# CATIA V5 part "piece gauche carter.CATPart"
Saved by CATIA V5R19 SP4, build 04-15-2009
Part number: piece gauche carter
Bounding box of the stored display mesh (mm): x 0 to 17.7, y -143.505 to 592.858, z -82.118 to 132.474
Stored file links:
  G:\EU_thinkMotion\CFAO_2010\MMS_groupe1\MMS_groupe1\A reprendre\OK\rdeneffle\piece gauche carter.CATPart
  G:\EU_thinkMotion\CFAO_2010\MMS_groupe1\MMS_groupe1\A reprendre\OK\rdeneffle\piece haute carter.CATPart
  G:\EU_thinkMotion\CFAO_2010\MMS_groupe1\MMS_groupe1\A reprendre\OK\rdeneffle\systeme d'ouverture de porte de voiture.CATProduct
  G:\EU_thinkMotion\CFAO_2010\MMS_groupe1\MMS_groupe1\A reprendre\OK\rdeneffle\squelette.CATPart
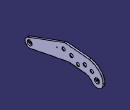
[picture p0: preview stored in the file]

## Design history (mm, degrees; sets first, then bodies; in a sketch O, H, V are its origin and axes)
Set1
  Line1 to Line6: linked copy from another document
Body1 (main body)
Body2
  Sketch1 on yz-plane, origin (0, 0, 0), H (0, 1, 0), V (0, 0, 1)
    line L1 (-115.8569, 5.5867) -> (231.1101, 133.3715)
    line L2 (-92.9007, -75.9825) -> (265.6157, -4.8754)
    arc A1 centre (-101.169, -34.2945) radius 42.5 from (-115.8569, 5.5867) to (-92.9007, -75.9825) ccw
    point P5 (-101.169, -34.2945)
    line L3 (231.1101, 133.3715) -> (463.899, 112.1961)
    point P6 (463.899, 112.1961)
    line L4 (265.6157, -4.8754) -> (417.9866, -18.7357)
    point P7 (417.9866, -18.7357)
    point P8 (535.8579, -25.2291)
    point P9 (498.4495, -68.2362)
    point P10 (573.2442, 17.7972)
    spline S1 through (463.899, 112.1961) (517.8359, 90.8537) (573.2442, 39.8908) (592.8579, -25.2291)
    spline S2 through (417.9866, -18.7357) (442.583, -22.9106) (473.0665, -41.2867) (498.4495, -68.2362) (498.4495, -68.2362)
    arc A2 centre (535.8579, -25.2291) radius 57 from (498.4495, -68.2362) to (592.8579, -25.2291) ccw
    point P12 (592.8579, -25.2291)
    point P13 (463.899, 112.1961)
    point P14 (592.8579, -25.2291)
    point P15 (417.9866, -18.7357)
    point P19 (498.4495, -68.2362)
    radius A1 = 42.5
    length L2 = 365.5
    angle L1 L2 = 9
    length L1 = 369.75
    length L3 = 233.75
    length L4 = 153
    distance P8 P6 = 155.125
    distance P7 P8 = 118.05
    radius A2 = 57
    distance P8 P5 = 637.0914
    tangency: A1 L1, L2 A1
    parallelism: L4 L3
    coincidence: P13 P6, P15 P7, P19 P9, A2 P10, P14 P12
  Pad1: profile Sketch1, direction (1, 0, 0), length 17.7
  Fillet1: radius 50, on edge [face of Pad1 from Sketch1.L1 | face of Pad1 from Sketch1.L3]
  Fillet2: radius 50, on edge [face of Pad1 from Sketch1.L4 | face of Pad1 from Sketch1.L2]
  Sketch2 on end face of Pad1, origin (17.7, 0, 0), H (0, 1, 0), V (0, 0, 1)
    circle A1 centre (535.8579, -25.2291) radius 13
    circle A2 centre (-101.169, -34.2945) radius 13
    reference projected arc E1 centre (-101.169, -34.2945) radius 42.5 from (-115.8569, 5.5867) to (-92.9007, -75.9825) ccw from edge [face of Pad1 from Sketch1.A1 | end face of Pad1]
    reference projected arc E2 centre (535.8579, -25.2291) radius 57 from (498.4495, -68.2362) to (592.8579, -25.2291) ccw from edge [face of Pad1 from Sketch1.A2 | end face of Pad1]
    radius A2 = 13
    radius A1 = 13
    concentricity: A2 E1, A1 E2
  Pocket1: profile Sketch2, direction (-1, 0, 0), length 17.7
  DatumCurve1
  Sketch3 on end face of Pad1, origin (17.7, 0, 0), H (0, 1, 0), V (0, 0, 1)
    circle A1 centre (-101.1686, -34.2944) radius 23.5
    reference projected circle E1 centre (-101.1686, -34.2944) radius 43 from edge of DatumCurve1
    radius A1 = 23.5
    concentricity: A1 E1
  Pocket2: profile Sketch3, direction (-1, 0, 0), length 13
  DatumCurve2
  Sketch4 on end face of Pad1, origin (17.7, 0, 0), H (0, 1, 0), V (0, 0, 1)
    circle A1 centre (535.8579, -25.2291) radius 23.5
    reference projected circle E1 centre (535.8579, -25.2291) radius 57 from edge of DatumCurve2
    radius A1 = 23.5
    concentricity: A1 E1
  Pocket3: profile Sketch4, direction (-1, 0, 0), length 13
  Sketch5 on end face of Pad1, origin (17.7, 0, 0), H (0, 1, 0), V (0, 0, 1)
    circle A1 centre (157.8475, 60.0892) radius 3.85
    point P1 (157.8475, 60.0892)
    circle A2 centre (219.6815, 76.7132) radius 15.505
    point P2 (219.6815, 76.7132)
    circle A3 centre (294.2515, 59.9231) radius 15.505
    point P3 (294.2515, 59.9231)
    circle A4 centre (356.8944, 18.1521) radius 15.505
    point P4 (356.8944, 18.1521)
    circle A5 centre (421.9525, 48.624) radius 15.505
    point P5 (421.9525, 48.624)
    circle A6 centre (488.2504, 26.056) radius 15.505
    point P6 (488.2504, 26.056)
    reference projected point E1 (157.8475, 60.0892) from Line1
    reference projected point E2 (219.6815, 76.7132) from Line2
    reference projected point E3 (294.2515, 59.9231) from Line3
    reference projected point E4 (356.8944, 18.1521) from Line4
    reference projected point E5 (421.9525, 48.624) from Line5
    reference projected point E6 (488.2504, 26.056) from Line6
    radius A1 = 3.85
    radius A2 = 15.505
    radius A3 = 15.505
    radius A4 = 15.505
    radius A5 = 15.505
    radius A6 = 15.505
    coincidence: P1 E1, P2 E2, P3 E3, P4 E4, P5 E5, E6 P6
  Pocket4: profile Sketch5, direction (-1, 0, 0), length 5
